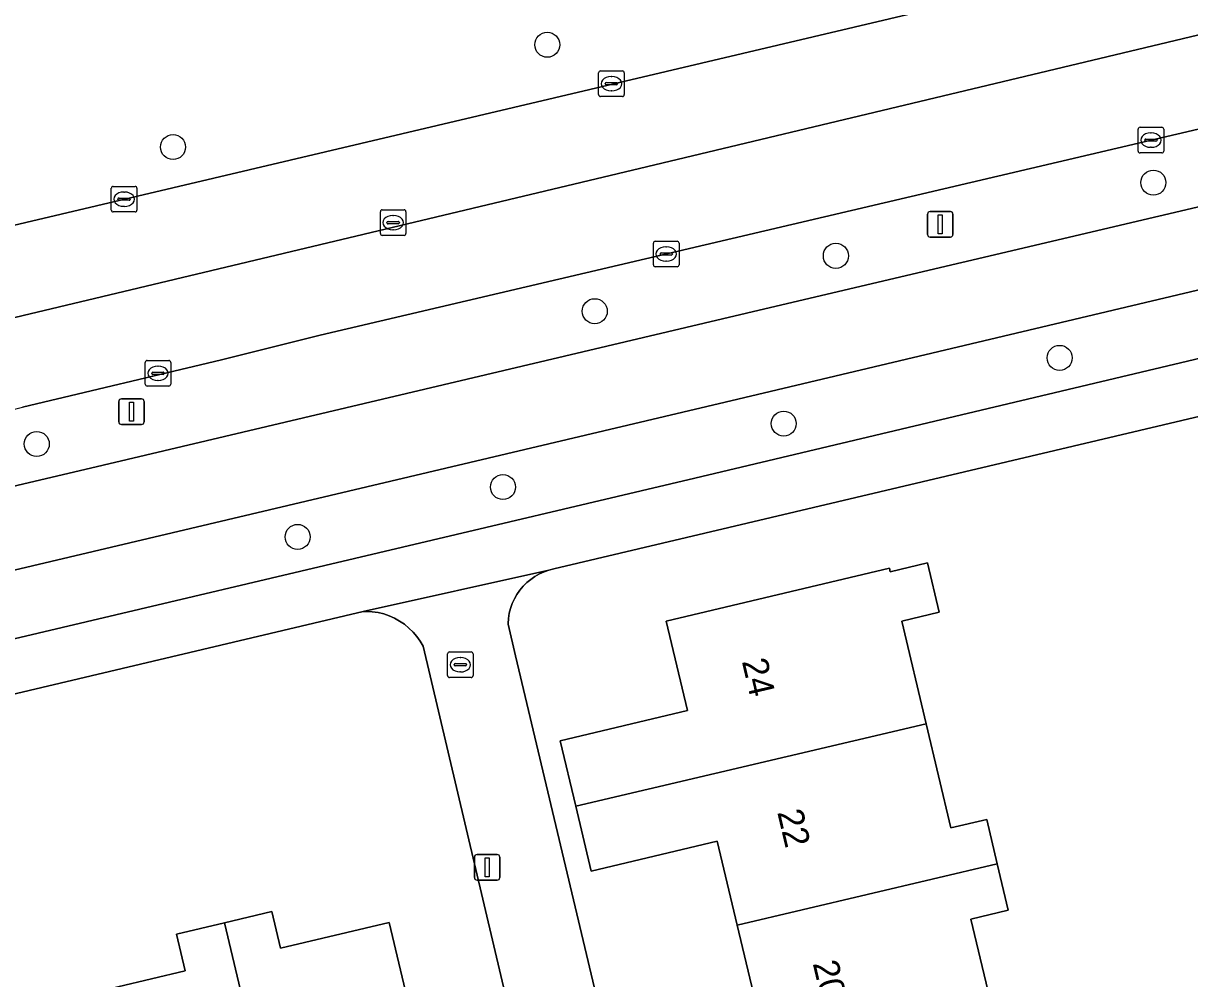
# Model space of a CAD drawing. Extents: x 158031 to 159244, y 380104 to 381214.
# Drawn here: x 158424.79 to 158470.39, y 380931.84 to 380969.19 of the extents above; entities that cross this region are included whole.
import ezdxf

# ---------------------------------------------------------------- set-up
doc = ezdxf.new("R2010")
doc.units = 0
for name, color, linetype in [('IMGEO_Berm_groen', 7, 'Continuous'), ('IMGEO_Boom', 7, 'Continuous'), ('IMGEO_Brandkraan', 7, 'Continuous'), ('IMGEO_Erf', 7, 'Continuous'), ('IMGEO_Fietspad_open', 7, 'Continuous'), ('IMGEO_Groenvoorziening', 7, 'Continuous'), ('IMGEO_Kolk', 7, 'Continuous'), ('IMGEO_Lichtmast', 7, 'Continuous'), ('IMGEO_Pand', 7, 'Continuous'), ('IMGEO_Pand_nummerreeks', 7, 'Continuous'), ('IMGEO_Rijbaan_regionaal_gesloten', 7, 'Continuous'), ('IMGEO_Rioolput', 7, 'Continuous'), ('IMGEO_Voetpad_open', 7, 'Continuous')]:
    doc.layers.add(name, color=color, linetype=linetype)

msp = doc.modelspace()

# ---------------------------------------------------------------- linework, layer by layer
at = {"layer": 'IMGEO_Berm_groen'}
for points in [[(158500, 380968.887), (158515.75, 380972.588), (158534.976, 380977.093), (158542.093, 380977.956), (158541.87, 380980.039), (158541.552, 380980.099), (158539.295, 380980.464), (158537.581, 380980.459), (158534.98, 380980.193), (158511.801, 380974.708), (158500, 380971.935), (158436.396, 380956.989), (158432.537, 380956.03), (158424.755, 380954.177)], [(158421.479, 380950.398), (158427.193, 380951.747), (158453.778, 380958.024), (158500, 380968.887)]]:
    msp.add_lwpolyline(points, dxfattribs=at)
msp.add_lwpolyline([(158500, 380963.025), (158504.694, 380964.14), (158541.178, 380972.748), (158543.921, 380973.246), (158543.487, 380975.057), (158534.95, 380974.009), (158529.941, 380972.799), (158500, 380965.696), (158452.232, 380954.381), (158411.121, 380944.673), (158374, 380935.945), (158368.915, 380934.535), (158365.009, 380933.393), (158364.501, 380933.162), (158364.97, 380931.086), (158401.56, 380939.73), (158451.051, 380951.403)], close=True, dxfattribs=at)
at = {"layer": 'IMGEO_Boom'}
for centre in [(158445.278, 380968.347), (158430.644, 380964.349), (158468.975, 380962.957), (158456.56, 380960.096), (158447.134, 380957.932), (158465.31, 380956.108), (158454.522, 380953.537), (158425.317, 380952.741), (158443.545, 380951.057), (158435.517, 380949.109)]:
    msp.add_circle(centre, 0.489, dxfattribs=at)
at = {"layer": 'IMGEO_Brandkraan'}
for p, q in [((158441.378, 380943.683), (158441.378, 380944.535)), ((158441.453, 380944.609), (158442.305, 380944.609)), ((158441.866, 380944.389), (158441.891, 380944.389)), ((158442.379, 380944.535), (158442.379, 380943.683)), ((158441.637, 380944.103), (158441.637, 380944.115)), ((158442.075, 380944.066), (158441.677, 380944.066)), ((158441.68, 380944.152), (158442.078, 380944.152)), ((158441.889, 380943.829), (158441.864, 380943.829)), ((158442.121, 380944.115), (158442.121, 380944.103)), ((158442.305, 380943.609), (158441.453, 380943.609))]:
    msp.add_line(p, q, dxfattribs=at)
for points in [[(158441.378, 380943.683), (158441.378, 380944.535)], [(158441.453, 380944.609), (158442.305, 380944.609)], [(158442.379, 380944.535), (158442.379, 380943.683)], [(158442.305, 380943.609), (158441.453, 380943.609)]]:
    msp.add_lwpolyline(points, dxfattribs=at)
for centre, radius, start, end in [((158441.455, 380944.533), 0.0765, 91.552, 178.448), ((158441.455, 380944.533), 0.0765, 91.552, 178.448), ((158442.303, 380944.533), 0.0765, 1.552, 88.448), ((158442.303, 380944.533), 0.0765, 1.552, 88.448), ((158441.677, 380944.112), 0.0403, 85.8775, 175.7526), ((158441.674, 380944.102), 0.0366, 178.938, 274.7102), ((158442.078, 380944.109), 0.043, 264.8664, 352.4533), ((158442.082, 380944.114), 0.0386, 1.7309, 96.639), ((158441.455, 380943.685), 0.0765, 181.552, 268.448), ((158441.455, 380943.685), 0.0765, 181.552, 268.448), ((158442.303, 380943.685), 0.0765, 271.552, 358.448), ((158442.303, 380943.685), 0.0765, 271.552, 358.448)]:
    msp.add_arc(centre, radius, start, end, dxfattribs=at)
for centre, major_axis, ratio, start_param, end_param in [((158441.865, 380944.109), (-0.387, 0.002), 0.722429, 4.712389, 7.853982), ((158441.89, 380944.109), (-0.39, 0.002), 0.717154, 1.570796, 4.712389)]:
    msp.add_ellipse(centre, major_axis=major_axis, ratio=ratio, start_param=start_param, end_param=end_param, dxfattribs=at)
at = {"layer": 'IMGEO_Erf'}
for points in [[(158487.077, 380957.668), (158445.535, 380947.858), (158445.341, 380947.809), (158445.151, 380947.743), (158444.969, 380947.66), (158444.794, 380947.562), (158444.629, 380947.448), (158444.475, 380947.319), (158444.333, 380947.178), (158444.204, 380947.025), (158444.09, 380946.86), (158443.99, 380946.686), (158443.907, 380946.504), (158443.84, 380946.315), (158443.79, 380946.121), (158443.758, 380945.923), (158443.744, 380945.723), (158443.743, 380945.698), (158444.036, 380944.464), (158450.525, 380917.157), (158453.959, 380902.708), (158454.373, 380900.966), (158455.935, 380901.337), (158498.672, 380911.466)], [(158453.481, 380930.658), (158452.704, 380933.929), (158451.925, 380937.207), (158446.998, 380936.037), (158446.393, 380938.585), (158445.787, 380941.138), (158450.755, 380942.318), (158449.924, 380945.816), (158458.655, 380947.889), (158458.688, 380947.748), (158460.142, 380948.093), (158460.6, 380946.166), (158459.14, 380945.819), (158460.094, 380941.803), (158461.061, 380937.733), (158462.459, 380938.065), (158462.873, 380936.323), (158463.303, 380934.514), (158461.842, 380934.167), (158462.799, 380930.137)], [(158445.631, 380922.784), (158440.697, 380943.674), (158440.424, 380944.831), (158440.31, 380945.028), (158440.178, 380945.213), (158440.03, 380945.387), (158439.868, 380945.546), (158439.692, 380945.69), (158439.503, 380945.818), (158439.304, 380945.928), (158439.096, 380946.021), (158438.881, 380946.094), (158438.66, 380946.148), (158438.435, 380946.182), (158438.207, 380946.195), (158438.078, 380946.194), (158365.77, 380929.098)], [(158427.164, 380931.206), (158431.123, 380932.149), (158430.783, 380933.572), (158432.66, 380934.019), (158434.502, 380934.458), (158434.843, 380933.025), (158439.094, 380934.038), (158441.185, 380925.264)]]:
    msp.add_lwpolyline(points, dxfattribs=at)
at = {"layer": 'IMGEO_Fietspad_open'}
for points in [[(158668.967, 381005.563), (158668.216, 381008.625), (158666.916, 381008.345), (158664.276, 381007.743), (158655.094, 381005.47), (158646, 381002.859), (158637.012, 380999.915), (158631.65, 380998.147), (158625.313, 380996.031), (158588.305, 380987.098), (158584.646, 380986.212), (158559.031, 380980.009), (158542.093, 380977.956), (158534.976, 380977.093), (158515.75, 380972.588), (158500, 380968.887), (158453.778, 380958.024), (158427.193, 380951.747), (158421.479, 380950.398)], [(158364.501, 380933.162), (158365.009, 380933.393), (158368.915, 380934.535), (158374, 380935.945), (158411.121, 380944.673), (158452.232, 380954.381), (158500, 380965.696), (158529.941, 380972.799)]]:
    msp.add_lwpolyline(points, dxfattribs=at)
at = {"layer": 'IMGEO_Groenvoorziening'}
msp.add_lwpolyline([(158369.389, 380964.254), (158363.858, 380976.351), (158356.258, 380974.547), (158372.396, 380952.401), (158373.204, 380949.217), (158500, 380979.117), (158570.711, 380995.952)], dxfattribs=at)
at = {"layer": 'IMGEO_Kolk'}
for p, q in [((158447.286, 380966.398), (158447.286, 380967.25)), ((158447.361, 380967.324), (158448.213, 380967.324)), ((158447.774, 380967.104), (158447.799, 380967.104)), ((158448.287, 380967.25), (158448.287, 380966.398)), ((158447.545, 380966.818), (158447.545, 380966.83)), ((158447.983, 380966.781), (158447.585, 380966.781)), ((158447.588, 380966.867), (158447.986, 380966.867)), ((158448.029, 380966.83), (158448.029, 380966.818)), ((158448.213, 380966.324), (158447.361, 380966.324)), ((158447.797, 380966.544), (158447.772, 380966.544)), ((158468.379, 380964.194), (158468.379, 380965.046)), ((158468.454, 380965.12), (158469.306, 380965.12)), ((158468.867, 380964.9), (158468.892, 380964.9)), ((158469.38, 380965.046), (158469.38, 380964.194)), ((158468.638, 380964.614), (158468.638, 380964.626)), ((158469.076, 380964.577), (158468.678, 380964.577)), ((158468.681, 380964.663), (158469.079, 380964.663)), ((158468.89, 380964.34), (158468.865, 380964.34)), ((158469.122, 380964.626), (158469.122, 380964.614)), ((158469.306, 380964.12), (158468.454, 380964.12)), ((158428.232, 380961.885), (158428.232, 380962.737)), ((158428.307, 380962.811), (158429.159, 380962.811)), ((158428.72, 380962.591), (158428.745, 380962.591)), ((158429.233, 380962.737), (158429.233, 380961.885)), ((158428.491, 380962.305), (158428.491, 380962.317)), ((158428.929, 380962.268), (158428.531, 380962.268)), ((158428.534, 380962.354), (158428.932, 380962.354)), ((158428.975, 380962.317), (158428.975, 380962.305)), ((158429.159, 380961.811), (158428.307, 380961.811)), ((158428.743, 380962.031), (158428.718, 380962.031)), ((158449.427, 380959.741), (158449.427, 380960.593)), ((158449.502, 380960.667), (158450.354, 380960.667)), ((158449.915, 380960.447), (158449.94, 380960.447)), ((158450.428, 380960.593), (158450.428, 380959.741)), ((158449.686, 380960.161), (158449.686, 380960.173)), ((158450.124, 380960.124), (158449.726, 380960.124)), ((158449.729, 380960.21), (158450.127, 380960.21)), ((158449.938, 380959.887), (158449.913, 380959.887)), ((158450.17, 380960.173), (158450.17, 380960.161)), ((158450.354, 380959.667), (158449.502, 380959.667)), ((158429.557, 380955.078), (158429.557, 380955.93)), ((158429.632, 380956.004), (158430.484, 380956.004)), ((158430.045, 380955.784), (158430.07, 380955.784)), ((158430.558, 380955.93), (158430.558, 380955.078)), ((158429.816, 380955.498), (158429.816, 380955.51)), ((158430.254, 380955.461), (158429.856, 380955.461)), ((158429.859, 380955.547), (158430.257, 380955.547)), ((158430.068, 380955.224), (158430.043, 380955.224)), ((158430.3, 380955.51), (158430.3, 380955.498)), ((158430.484, 380955.004), (158429.632, 380955.004))]:
    msp.add_line(p, q, dxfattribs=at)
for points in [[(158447.286, 380966.398), (158447.286, 380967.25)], [(158447.361, 380967.324), (158448.213, 380967.324)], [(158448.287, 380967.25), (158448.287, 380966.398)], [(158448.213, 380966.324), (158447.361, 380966.324)], [(158468.379, 380964.194), (158468.379, 380965.046)], [(158468.454, 380965.12), (158469.306, 380965.12)], [(158469.38, 380965.046), (158469.38, 380964.194)], [(158469.306, 380964.12), (158468.454, 380964.12)], [(158428.232, 380961.885), (158428.232, 380962.737)], [(158428.307, 380962.811), (158429.159, 380962.811)], [(158429.233, 380962.737), (158429.233, 380961.885)], [(158429.159, 380961.811), (158428.307, 380961.811)], [(158449.427, 380959.741), (158449.427, 380960.593)], [(158449.502, 380960.667), (158450.354, 380960.667)], [(158450.428, 380960.593), (158450.428, 380959.741)], [(158450.354, 380959.667), (158449.502, 380959.667)], [(158429.557, 380955.078), (158429.557, 380955.93)], [(158429.632, 380956.004), (158430.484, 380956.004)], [(158430.558, 380955.93), (158430.558, 380955.078)], [(158430.484, 380955.004), (158429.632, 380955.004)]]:
    msp.add_lwpolyline(points, dxfattribs=at)
for centre, radius, start, end in [((158447.363, 380967.248), 0.0765, 91.552, 178.448), ((158447.363, 380967.248), 0.0765, 91.552, 178.448), ((158448.211, 380967.248), 0.0765, 1.552, 88.448), ((158448.211, 380967.248), 0.0765, 1.552, 88.448), ((158447.585, 380966.827), 0.0403, 85.8775, 175.7526), ((158447.582, 380966.817), 0.0366, 178.938, 274.7102), ((158447.986, 380966.824), 0.043, 264.8664, 352.4533), ((158447.99, 380966.829), 0.0386, 1.7309, 96.639), ((158447.363, 380966.4), 0.0765, 181.552, 268.448), ((158447.363, 380966.4), 0.0765, 181.552, 268.448), ((158448.211, 380966.4), 0.0765, 271.552, 358.448), ((158448.211, 380966.4), 0.0765, 271.552, 358.448), ((158468.456, 380965.044), 0.0765, 91.552, 178.448), ((158468.456, 380965.044), 0.0765, 91.552, 178.448), ((158469.304, 380965.044), 0.0765, 1.552, 88.448), ((158469.304, 380965.044), 0.0765, 1.552, 88.448), ((158468.678, 380964.623), 0.0403, 85.8775, 175.7526), ((158468.675, 380964.613), 0.0366, 178.938, 274.7102), ((158469.079, 380964.62), 0.043, 264.8664, 352.4533), ((158469.083, 380964.625), 0.0386, 1.7309, 96.639), ((158468.456, 380964.196), 0.0765, 181.552, 268.448), ((158468.456, 380964.196), 0.0765, 181.552, 268.448), ((158469.304, 380964.196), 0.0765, 271.552, 358.448), ((158469.304, 380964.196), 0.0765, 271.552, 358.448), ((158428.309, 380962.735), 0.0765, 91.552, 178.448), ((158428.309, 380962.735), 0.0765, 91.552, 178.448), ((158429.157, 380962.735), 0.0765, 1.552, 88.448), ((158429.157, 380962.735), 0.0765, 1.552, 88.448), ((158428.531, 380962.314), 0.0403, 85.8775, 175.7526), ((158428.528, 380962.304), 0.0366, 178.938, 274.7102), ((158428.932, 380962.311), 0.043, 264.8664, 352.4533), ((158428.936, 380962.316), 0.0386, 1.7309, 96.639), ((158428.309, 380961.887), 0.0765, 181.552, 268.448), ((158428.309, 380961.887), 0.0765, 181.552, 268.448), ((158429.157, 380961.887), 0.0765, 271.552, 358.448), ((158429.157, 380961.887), 0.0765, 271.552, 358.448), ((158449.504, 380960.591), 0.0765, 91.552, 178.448), ((158449.504, 380960.591), 0.0765, 91.552, 178.448), ((158450.352, 380960.591), 0.0765, 1.552, 88.448), ((158450.352, 380960.591), 0.0765, 1.552, 88.448), ((158449.726, 380960.17), 0.0403, 85.8775, 175.7526), ((158449.723, 380960.16), 0.0366, 178.938, 274.7102), ((158450.127, 380960.167), 0.043, 264.8664, 352.4533), ((158450.131, 380960.172), 0.0386, 1.7309, 96.639), ((158449.504, 380959.743), 0.0765, 181.552, 268.448), ((158449.504, 380959.743), 0.0765, 181.552, 268.448), ((158450.352, 380959.743), 0.0765, 271.552, 358.448), ((158450.352, 380959.743), 0.0765, 271.552, 358.448), ((158429.634, 380955.928), 0.0765, 91.552, 178.448), ((158429.634, 380955.928), 0.0765, 91.552, 178.448), ((158430.482, 380955.928), 0.0765, 1.552, 88.448), ((158430.482, 380955.928), 0.0765, 1.552, 88.448), ((158429.856, 380955.507), 0.0403, 85.8775, 175.7526), ((158429.853, 380955.497), 0.0366, 178.938, 274.7102), ((158430.257, 380955.504), 0.043, 264.8664, 352.4533), ((158430.261, 380955.509), 0.0386, 1.7309, 96.639), ((158429.634, 380955.08), 0.0765, 181.552, 268.448), ((158429.634, 380955.08), 0.0765, 181.552, 268.448), ((158430.482, 380955.08), 0.0765, 271.552, 358.448), ((158430.482, 380955.08), 0.0765, 271.552, 358.448)]:
    msp.add_arc(centre, radius, start, end, dxfattribs=at)
for centre, major_axis, ratio, start_param, end_param in [((158447.773, 380966.824), (-0.387, 0.002), 0.722429, 4.712389, 7.853982), ((158447.798, 380966.824), (-0.39, 0.002), 0.717154, 1.570796, 4.712389), ((158468.866, 380964.62), (-0.387, 0.002), 0.722429, 4.712389, 7.853982), ((158468.891, 380964.62), (-0.39, 0.002), 0.717154, 1.570796, 4.712389), ((158428.719, 380962.311), (-0.387, 0.002), 0.722429, 4.712389, 7.853982), ((158428.744, 380962.311), (-0.39, 0.002), 0.717154, 1.570796, 4.712389), ((158449.914, 380960.167), (-0.387, 0.002), 0.722429, 4.712389, 7.853982), ((158449.939, 380960.167), (-0.39, 0.002), 0.717154, 1.570796, 4.712389), ((158430.044, 380955.504), (-0.387, 0.002), 0.722429, 4.712389, 7.853982), ((158430.069, 380955.504), (-0.39, 0.002), 0.717154, 1.570796, 4.712389)]:
    msp.add_ellipse(centre, major_axis=major_axis, ratio=ratio, start_param=start_param, end_param=end_param, dxfattribs=at)
at = {"layer": 'IMGEO_Lichtmast'}
for p, q in [((158460.147, 380960.93), (158460.147, 380961.73)), ((158460.147, 380961.73), (158460.147, 380960.93)), ((158460.247, 380961.83), (158461.037, 380961.83)), ((158461.037, 380961.83), (158460.247, 380961.83)), ((158461.137, 380961.73), (158461.137, 380960.93)), ((158461.137, 380960.93), (158461.137, 380961.73)), ((158461.037, 380960.83), (158460.247, 380960.83)), ((158460.247, 380960.83), (158461.037, 380960.83)), ((158428.524, 380953.603), (158428.524, 380954.403)), ((158428.524, 380954.403), (158428.524, 380953.603)), ((158428.624, 380954.503), (158429.414, 380954.503)), ((158429.414, 380954.503), (158428.624, 380954.503)), ((158429.514, 380954.403), (158429.514, 380953.603)), ((158429.514, 380953.603), (158429.514, 380954.403)), ((158429.414, 380953.503), (158428.624, 380953.503)), ((158428.624, 380953.503), (158429.414, 380953.503)), ((158442.43, 380935.791), (158442.43, 380936.591)), ((158442.43, 380936.591), (158442.43, 380935.791)), ((158442.53, 380936.691), (158443.32, 380936.691)), ((158443.32, 380936.691), (158442.53, 380936.691)), ((158443.42, 380936.591), (158443.42, 380935.791)), ((158443.42, 380935.791), (158443.42, 380936.591)), ((158443.32, 380935.691), (158442.53, 380935.691)), ((158442.53, 380935.691), (158443.32, 380935.691))]:
    msp.add_line(p, q, dxfattribs=at)
for points in [[(158460.567, 380961.705), (158460.717, 380961.705), (158460.717, 380960.955), (158460.567, 380960.955), (158460.567, 380961.705)], [(158428.944, 380954.378), (158429.094, 380954.378), (158429.094, 380953.628), (158428.944, 380953.628), (158428.944, 380954.378)], [(158442.85, 380936.566), (158443, 380936.566), (158443, 380935.816), (158442.85, 380935.816), (158442.85, 380936.566)]]:
    msp.add_lwpolyline(points, dxfattribs=at)
for centre, start, end in [((158460.247, 380961.73), 90, 180), ((158460.247, 380961.73), 90, 180), ((158461.037, 380961.73), 0, 90), ((158461.037, 380961.73), 360, 90), ((158460.247, 380960.93), 180, 270), ((158460.247, 380960.93), 180, 270), ((158461.037, 380960.93), 270, 0), ((158461.037, 380960.93), 270, 0), ((158428.624, 380954.403), 90, 180), ((158428.624, 380954.403), 90, 180), ((158429.414, 380954.403), 0, 90), ((158429.414, 380954.403), 360, 90), ((158428.624, 380953.603), 180, 270), ((158428.624, 380953.603), 180, 270), ((158429.414, 380953.603), 270, 0), ((158429.414, 380953.603), 270, 0), ((158442.53, 380936.591), 90, 180), ((158442.53, 380936.591), 90, 180), ((158443.32, 380936.591), 0, 90), ((158443.32, 380936.591), 360, 90), ((158442.53, 380935.791), 180, 270), ((158442.53, 380935.791), 180, 270), ((158443.32, 380935.791), 270, 0), ((158443.32, 380935.791), 270, 0)]:
    msp.add_arc(centre, 0.1, start, end, dxfattribs=at)
at = {"layer": 'IMGEO_Pand'}
for points in [[(158460.094, 380941.803), (158459.14, 380945.819), (158460.6, 380946.166), (158460.142, 380948.093), (158458.688, 380947.748), (158458.655, 380947.889), (158449.924, 380945.816), (158450.755, 380942.318), (158445.787, 380941.138), (158446.393, 380938.585)], [(158452.704, 380933.929), (158462.873, 380936.323), (158462.459, 380938.065), (158461.061, 380937.733), (158460.094, 380941.803), (158446.393, 380938.585), (158446.998, 380936.037), (158451.925, 380937.207)], [(158449.103, 380926.916), (158462.799, 380930.137), (158461.842, 380934.167), (158463.303, 380934.514), (158462.873, 380936.323), (158452.704, 380933.929), (158453.481, 380930.658), (158448.495, 380929.474)], [(158432.66, 380934.019), (158436.272, 380918.825), (158438.837, 380919.436), (158437.649, 380924.422), (158441.185, 380925.264), (158439.094, 380934.038), (158434.843, 380933.025), (158434.502, 380934.458)], [(158429.208, 380922.421), (158432.488, 380923.203), (158433.678, 380918.207), (158436.272, 380918.825), (158432.66, 380934.019), (158430.783, 380933.572), (158431.123, 380932.149), (158427.164, 380931.206)]]:
    msp.add_lwpolyline(points, close=True, dxfattribs=at)
at = {"layer": 'IMGEO_Rijbaan_regionaal_gesloten'}
for points in [[(158570.711, 380995.952), (158500, 380979.117), (158373.204, 380949.217), (158362.848, 380946.775), (158359.897, 380946.084), (158360.018, 380942.318), (158448.885, 380963.516), (158460.444, 380966.274), (158472.175, 380969.072), (158483.617, 380971.741), (158491.19, 380973.547), (158514.329, 380979.065), (158522.041, 380980.853), (158529.678, 380982.624), (158537.46, 380984.502), (158545.06, 380986.275), (158548.941, 380987.249), (158556.721, 380989.087), (158560.604, 380990.004), (158568.275, 380991.816)], [(158568.275, 380991.816), (158560.604, 380990.004), (158556.721, 380989.087), (158548.941, 380987.249), (158545.06, 380986.275), (158537.46, 380984.502), (158529.678, 380982.624), (158522.041, 380980.853), (158514.329, 380979.065), (158491.19, 380973.547), (158483.617, 380971.741), (158472.175, 380969.072), (158460.444, 380966.274), (158448.885, 380963.516), (158360.018, 380942.318)], [(158362.718, 380939.535), (158381.814, 380944.216), (158413.082, 380951.39), (158419.433, 380952.857), (158424.755, 380954.177), (158432.537, 380956.03), (158436.396, 380956.989), (158500, 380971.935), (158511.801, 380974.708), (158534.98, 380980.193), (158571.869, 380988.984)]]:
    msp.add_lwpolyline(points, dxfattribs=at)
at = {"layer": 'IMGEO_Rioolput'}
for p, q in [((158438.751, 380960.969), (158438.751, 380961.821)), ((158438.826, 380961.895), (158439.678, 380961.895)), ((158439.239, 380961.675), (158439.264, 380961.675)), ((158439.752, 380961.821), (158439.752, 380960.969)), ((158439.01, 380961.389), (158439.01, 380961.401)), ((158439.448, 380961.352), (158439.05, 380961.352)), ((158439.053, 380961.438), (158439.451, 380961.438)), ((158439.494, 380961.401), (158439.494, 380961.389)), ((158439.678, 380960.895), (158438.826, 380960.895)), ((158439.262, 380961.115), (158439.237, 380961.115))]:
    msp.add_line(p, q, dxfattribs=at)
for points in [[(158438.751, 380960.969), (158438.751, 380961.821)], [(158438.826, 380961.895), (158439.678, 380961.895)], [(158439.752, 380961.821), (158439.752, 380960.969)], [(158439.678, 380960.895), (158438.826, 380960.895)]]:
    msp.add_lwpolyline(points, dxfattribs=at)
for centre, radius, start, end in [((158438.828, 380961.819), 0.0765, 91.552, 178.448), ((158438.828, 380961.819), 0.0765, 91.552, 178.448), ((158439.676, 380961.819), 0.0765, 1.552, 88.448), ((158439.676, 380961.819), 0.0765, 1.552, 88.448), ((158439.05, 380961.398), 0.0403, 85.8775, 175.7526), ((158439.047, 380961.388), 0.0366, 178.938, 274.7102), ((158439.451, 380961.395), 0.043, 264.8664, 352.4533), ((158439.455, 380961.4), 0.0386, 1.7309, 96.639), ((158438.828, 380960.971), 0.0765, 181.552, 268.448), ((158438.828, 380960.971), 0.0765, 181.552, 268.448), ((158439.676, 380960.971), 0.0765, 271.552, 358.448), ((158439.676, 380960.971), 0.0765, 271.552, 358.448)]:
    msp.add_arc(centre, radius, start, end, dxfattribs=at)
for centre, major_axis, ratio, start_param, end_param in [((158439.238, 380961.395), (-0.387, 0.002), 0.722429, 4.712389, 7.853982), ((158439.263, 380961.395), (-0.39, 0.002), 0.717154, 1.570796, 4.712389)]:
    msp.add_ellipse(centre, major_axis=major_axis, ratio=ratio, start_param=start_param, end_param=end_param, dxfattribs=at)
at = {"layer": 'IMGEO_Voetpad_open'}
for points in [[(158646.352, 380999.546), (158629.543, 380993.657), (158628.561, 380993.352), (158626.388, 380992.815), (158613.803, 380989.844), (158590.087, 380984.449), (158585.768, 380983.41), (158569.881, 380979.588), (158559.5, 380977.024), (158543.487, 380975.057), (158543.921, 380973.246), (158541.178, 380972.748), (158504.694, 380964.14), (158500, 380963.025), (158451.051, 380951.403), (158401.56, 380939.73), (158364.97, 380931.086)], [(158365.77, 380929.098), (158438.078, 380946.194), (158445.341, 380947.809), (158445.535, 380947.858), (158487.077, 380957.668), (158487.122, 380957.681), (158494.072, 380959.329), (158494.125, 380959.337), (158500, 380960.729), (158530.996, 380968.075)], [(158450.525, 380917.157), (158444.036, 380944.464), (158443.743, 380945.698), (158443.744, 380945.723), (158443.758, 380945.923), (158443.79, 380946.121), (158443.84, 380946.315), (158443.907, 380946.504), (158443.99, 380946.686), (158444.09, 380946.86), (158444.204, 380947.025), (158444.333, 380947.178), (158444.475, 380947.319), (158444.629, 380947.448), (158444.794, 380947.562), (158444.969, 380947.66), (158445.151, 380947.743), (158445.341, 380947.809), (158438.078, 380946.194), (158438.207, 380946.195), (158438.435, 380946.182), (158438.66, 380946.148), (158438.881, 380946.094), (158439.096, 380946.021), (158439.304, 380945.928), (158439.503, 380945.818), (158439.692, 380945.69), (158439.868, 380945.546), (158440.03, 380945.387), (158440.178, 380945.213), (158440.31, 380945.028), (158440.424, 380944.831), (158440.697, 380943.674), (158445.631, 380922.784)]]:
    msp.add_lwpolyline(points, dxfattribs=at)

# ---------------------------------------------------------------- texts
at = {"layer": 'IMGEO_Pand_nummerreeks'}
for s, p in [('24', (158452.881, 380944.245)), ('22', (158454.266, 380938.346)), ('20', (158455.653, 380932.437))]:
    msp.add_text(s, height=1, rotation=283.2084, dxfattribs=at).set_placement(p)

doc.saveas('drawing.dxf')
